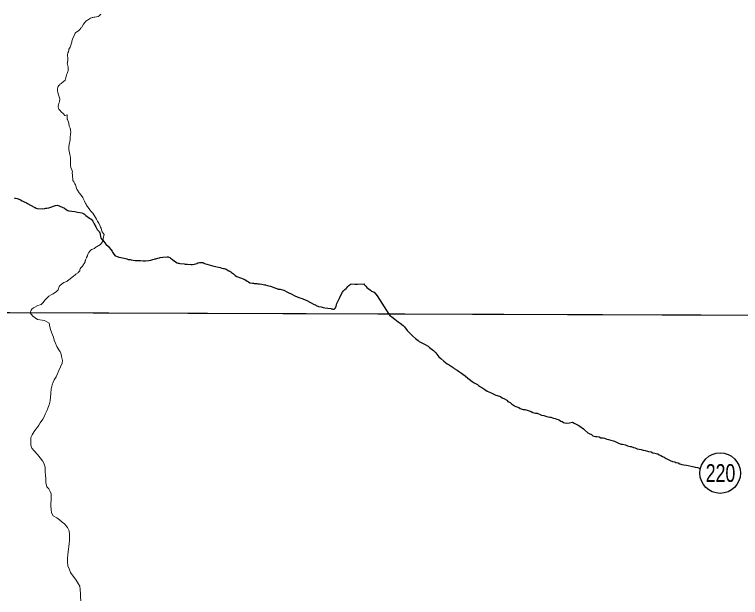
# Model space of a CAD drawing. Extents: x -1643653 to 4543381, y 1624270 to 13878484.
# Drawn here: x 592680 to 595557, y 8908816 to 8911127 of the extents above; entities that cross this region are included whole.
import ezdxf
from ezdxf.enums import TextEntityAlignment as Align

# ---------------------------------------------------------------- set-up
doc = ezdxf.new("R2010")
doc.units = 0
doc.header["$LTSCALE"] = 200
doc.layers.add('1', color=7, linetype='Continuous', lineweight=13)
doc.layers.add('6', color=7, linetype='Continuous', lineweight=13)

msp = doc.modelspace()

# ---------------------------------------------------------------- linework, layer by layer
at = {"layer": '1', "lineweight": 25}
msp.add_spline([(814781, 9009175.5), (814787.2, 9009173.4), (814796.9, 9009173.4), (814799.4, 9009172.4), (814805.1, 9009174.5), (814805.6, 9009176.5), (814811.7, 9009179.5), (814811.7, 9009179.5), (814801.5, 9009181), (814790.7, 9009181.5), (814784.1, 9009183.1), (814777.4, 9009185.1), (814778.4, 9009175.5)], degree=3, dxfattribs=at)
at = {"layer": '6'}
msp.add_line((574653.9, 8910009.3), (626625.7, 8909822.1), dxfattribs=at)
for points in [[(593021, 8911127.6), (593015.2, 8911121.6), (593010.8, 8911119.1), (593005, 8911116.9), (592997.8, 8911116), (592994.4, 8911116), (592989.8, 8911115.5), (592987.6, 8911114.5), (592984.2, 8911113.6), (592980.7, 8911111.7), (592973.4, 8911106.8), (592964.4, 8911101.9), (592962.6, 8911100.6), (592957.6, 8911095.5), (592952.8, 8911088.5), (592945.7, 8911076.3), (592943.7, 8911074.8), (592942.5, 8911072.4), (592938.9, 8911066.9), (592933.7, 8911062.6), (592926.3, 8911058.4), (592923.2, 8911055.9), (592920.4, 8911052.5), (592916.1, 8911043.7), (592916.1, 8911043.7), (592909.6, 8911028.6)], [(593021, 8911127.6), (593015.2, 8911121.6), (593010.8, 8911119.1), (593005, 8911116.9), (592997.8, 8911116), (592994.4, 8911116), (592989.8, 8911115.5), (592987.6, 8911114.5), (592984.2, 8911113.6), (592980.7, 8911111.7), (592973.4, 8911106.8), (592964.4, 8911101.9), (592962.6, 8911100.6), (592957.6, 8911095.5), (592952.8, 8911088.5), (592945.7, 8911076.3), (592943.7, 8911074.8), (592942.5, 8911072.4), (592938.9, 8911066.9), (592933.7, 8911062.6), (592926.3, 8911058.4), (592923.2, 8911055.9), (592920.4, 8911052.5), (592916.1, 8911043.7), (592916.1, 8911043.7), (592909.6, 8911028.6)], [(592909.6, 8911028.6), (592908.5, 8911024.7), (592907.1, 8911020.9), (592906.4, 8911017), (592904.4, 8911009.3), (592899.9, 8910997.6), (592898, 8910993.9), (592895.4, 8910989.9), (592894.3, 8910985.6), (592892.9, 8910978.5), (592891.3, 8910974.3), (592890.1, 8910966.4), (592890.1, 8910963), (592891.2, 8910954.9), (592891, 8910946.7), (592888.9, 8910935.1), (592888.6, 8910931.1), (592889.2, 8910929.2), (592890.3, 8910922.9), (592892, 8910918.3), (592892.1, 8910914.2), (592892.6, 8910909.9), (592892.2, 8910904.3), (592891.6, 8910903.2), (592891.1, 8910901.2), (592887.7, 8910893.3), (592886, 8910888.3), (592883.8, 8910880.5), (592883, 8910875.6), (592881.9, 8910871.2), (592880.5, 8910867.1), (592879.4, 8910865.2), (592874.2, 8910861), (592864, 8910853.8), (592859.3, 8910850.9), (592858.7, 8910849.9), (592858.5, 8910848.3), (592855.2, 8910845), (592852.8, 8910840.8), (592850.9, 8910837.1), (592850.1, 8910832.8), (592850.2, 8910828.5), (592849.9, 8910824.2), (592850.6, 8910819.4), (592852.2, 8910812.2), (592853.7, 8910808.4), (592855.7, 8910804.2), (592858.1, 8910796.9), (592858.8, 8910793.1), (592857.3, 8910780.7), (592855.5, 8910775.7), (592853.5, 8910767.8), (592852.8, 8910763.4), (592852.9, 8910761.5), (592854.1, 8910755.4), (592855.6, 8910750.4), (592855.9, 8910749.9), (592858.7, 8910747.8), (592866.3, 8910739.6), (592871.8, 8910734.4), (592879.5, 8910726.3), (592880.3, 8910726.4), (592887.2, 8910728.8), (592887.9, 8910728.8), (592888, 8910711.7), (592888.2, 8910711.4), (592889.3, 8910711.1), (592894.6, 8910695.8), (592896.6, 8910683.7), (592899.7, 8910676), (592900.8, 8910672.1), (592901, 8910668.3), (592902.1, 8910660.6), (592901.9, 8910653.4), (592899.8, 8910637.4), (592899.7, 8910629.6), (592896.5, 8910611.5), (592895.3, 8910602.9), (592895.4, 8910595), (592895.3, 8910591.2), (592898.7, 8910571.6), (592900, 8910566.8), (592901.4, 8910558.8), (592901.9, 8910545.9), (592901.7, 8910528.6), (592902.9, 8910520.1), (592906.2, 8910511.7), (592908.7, 8910503.3), (592908.6, 8910499), (592909.8, 8910490.3), (592910, 8910481.9), (592910.6, 8910477.6), (592910.5, 8910473.3), (592911.1, 8910469.2), (592911.9, 8910467.9), (592912.4, 8910466.2), (592913.2, 8910465.7), (592913.5, 8910464.9), (592914.1, 8910464.3), (592914.6, 8910463), (592914.6, 8910463)], [(592909.6, 8911028.6), (592908.5, 8911024.7), (592907.1, 8911020.9), (592906.4, 8911017), (592904.4, 8911009.3), (592899.9, 8910997.6), (592898, 8910993.9), (592895.4, 8910989.9), (592894.3, 8910985.6), (592892.9, 8910978.5), (592891.3, 8910974.3), (592890.1, 8910966.4), (592890.1, 8910963), (592891.2, 8910954.9), (592891, 8910946.7), (592888.9, 8910935.1), (592888.6, 8910931.1), (592889.2, 8910929.2), (592890.3, 8910922.9), (592892, 8910918.3), (592892.1, 8910914.2), (592892.6, 8910909.9), (592892.2, 8910904.3), (592891.6, 8910903.2), (592891.1, 8910901.2), (592887.7, 8910893.3), (592886, 8910888.3), (592883.8, 8910880.5), (592883, 8910875.6), (592881.9, 8910871.2), (592880.5, 8910867.1), (592879.4, 8910865.2), (592874.2, 8910861), (592864, 8910853.8), (592859.3, 8910850.9), (592858.7, 8910849.9), (592858.5, 8910848.3), (592855.2, 8910845), (592852.8, 8910840.8), (592850.9, 8910837.1), (592850.1, 8910832.8), (592850.2, 8910828.5), (592849.9, 8910824.2), (592850.6, 8910819.4), (592852.2, 8910812.2), (592853.7, 8910808.4), (592855.7, 8910804.2), (592858.1, 8910796.9), (592858.8, 8910793.1), (592857.3, 8910780.7), (592855.5, 8910775.7), (592853.5, 8910767.8), (592852.8, 8910763.4), (592852.9, 8910761.5), (592854.1, 8910755.4), (592855.6, 8910750.4), (592855.9, 8910749.9), (592858.7, 8910747.8), (592866.3, 8910739.6), (592871.8, 8910734.4), (592879.5, 8910726.3), (592880.3, 8910726.4), (592887.2, 8910728.8), (592887.9, 8910728.8), (592888, 8910711.7), (592888.2, 8910711.4), (592889.3, 8910711.1), (592894.6, 8910695.8), (592896.6, 8910683.7), (592899.7, 8910676), (592900.8, 8910672.1), (592901, 8910668.3), (592902.1, 8910660.6), (592901.9, 8910653.4), (592899.8, 8910637.4), (592899.7, 8910629.6), (592896.5, 8910611.5), (592895.3, 8910602.9), (592895.4, 8910595), (592895.3, 8910591.2), (592898.7, 8910571.6), (592900, 8910566.8), (592901.4, 8910558.8), (592901.9, 8910545.9), (592901.7, 8910528.6), (592902.9, 8910520.1), (592906.2, 8910511.7), (592908.7, 8910503.3), (592908.6, 8910499), (592909.8, 8910490.3), (592910, 8910481.9), (592910.6, 8910477.6), (592910.5, 8910473.3), (592911.1, 8910469.2), (592911.9, 8910467.9), (592912.4, 8910466.2), (592913.2, 8910465.7), (592913.5, 8910464.9), (592914.1, 8910464.3), (592914.6, 8910463), (592914.6, 8910463)], [(592914.6, 8910463), (592915.4, 8910462.3), (592916.1, 8910460.3), (592918.7, 8910456), (592920.7, 8910451.9), (592922.6, 8910447.1), (592924.7, 8910438.7), (592926.3, 8910434.8), (592928.6, 8910430.4), (592936.2, 8910419.6), (592943.9, 8910410.6), (592949.8, 8910401.8), (592952, 8910397.9), (592953.5, 8910394.6), (592956.4, 8910386.7), (592959.2, 8910380.4), (592961.5, 8910377.9), (592961.8, 8910376.4), (592962.9, 8910374.8), (592964.8, 8910371.1), (592978.6, 8910352.2), (592983.7, 8910346.6), (592990.1, 8910338.8), (593000.6, 8910322.5), (593004.8, 8910315), (593008.5, 8910307.3), (593013.4, 8910299.5), (593019.4, 8910288), (593020.8, 8910284), (593022.5, 8910280.1), (593024.6, 8910273.2), (593027.6, 8910264.8), (593035.4, 8910254.4), (593030.7, 8910240.7), (593030.9, 8910230.2), (593020.1, 8910215.3), (592998.5, 8910201.7), (592997.4, 8910200.2), (592996.1, 8910199.2), (592992.6, 8910198.2), (592989.5, 8910197.1), (592988, 8910196.2), (592985.1, 8910195), (592981.8, 8910193.1), (592977.9, 8910188.9), (592974.2, 8910183.6), (592974, 8910182.8), (592973, 8910182.1), (592970.3, 8910177.3), (592968.2, 8910170.4), (592964.9, 8910164), (592964.4, 8910161.9), (592963.2, 8910159.9), (592962.2, 8910157.6), (592961.4, 8910154.6), (592960.4, 8910152.4), (592960.1, 8910150), (592958.9, 8910146.6), (592955.8, 8910140.3), (592954.4, 8910138.1), (592953.5, 8910135.8), (592948.4, 8910129), (592942.4, 8910123.1), (592939.8, 8910119.4), (592938, 8910115.1), (592938.7, 8910111.5), (592933.6, 8910105.6), (592931.8, 8910104.5), (592931.2, 8910103.5), (592922.2, 8910097.5), (592918.4, 8910094), (592914.6, 8910091.5), (592900.2, 8910078.7), (592890, 8910070.6), (592886.7, 8910068.4), (592875.2, 8910064.1), (592864.2, 8910056.5), (592861.2, 8910054.1), (592858.4, 8910051.3), (592856.3, 8910048.5), (592854.8, 8910044.2), (592853.8, 8910039.6), (592852, 8910035.6), (592849, 8910032.1), (592845.4, 8910028.7), (592832.4, 8910019.7), (592824.2, 8910015.7), (592815.9, 8910010.6), (592813, 8910008.1), (592806.8, 8910001.8), (592800.1, 8909994.6), (592792.6, 8909985.4), (592788.8, 8909981.5), (592784.8, 8909978), (592781.2, 8909976.4), (592771.7, 8909973.2), (592759.7, 8909967.1), (592755.4, 8909964.5), (592748.5, 8909959.2), (592745.1, 8909955.2), (592741.7, 8909944.4)], [(592914.6, 8910463), (592915.4, 8910462.3), (592916.1, 8910460.3), (592918.7, 8910456), (592920.7, 8910451.9), (592922.6, 8910447.1), (592924.7, 8910438.7), (592926.3, 8910434.8), (592928.6, 8910430.4), (592936.2, 8910419.6), (592943.9, 8910410.6), (592949.8, 8910401.8), (592952, 8910397.9), (592953.5, 8910394.6), (592956.4, 8910386.7), (592959.2, 8910380.4), (592961.5, 8910377.9), (592961.8, 8910376.4), (592962.9, 8910374.8), (592964.8, 8910371.1), (592978.6, 8910352.2), (592983.7, 8910346.6), (592990.1, 8910338.8), (593000.6, 8910322.5), (593004.8, 8910315), (593008.5, 8910307.3), (593013.4, 8910299.5), (593019.4, 8910288), (593020.8, 8910284), (593022.5, 8910280.1), (593024.6, 8910273.2), (593027.6, 8910264.8), (593035.4, 8910254.4), (593030.7, 8910240.7), (593030.9, 8910230.2), (593020.1, 8910215.3), (592998.5, 8910201.7), (592997.4, 8910200.2), (592996.1, 8910199.2), (592992.6, 8910198.2), (592989.5, 8910197.1), (592988, 8910196.2), (592985.1, 8910195), (592981.8, 8910193.1), (592977.9, 8910188.9), (592974.2, 8910183.6), (592974, 8910182.8), (592973, 8910182.1), (592970.3, 8910177.3), (592968.2, 8910170.4), (592964.9, 8910164), (592964.4, 8910161.9), (592963.2, 8910159.9), (592962.2, 8910157.6), (592961.4, 8910154.6), (592960.4, 8910152.4), (592960.1, 8910150), (592958.9, 8910146.6), (592955.8, 8910140.3), (592954.4, 8910138.1), (592953.5, 8910135.8), (592948.4, 8910129), (592942.4, 8910123.1), (592939.8, 8910119.4), (592938, 8910115.1), (592938.7, 8910111.5), (592933.6, 8910105.6), (592931.8, 8910104.5), (592931.2, 8910103.5), (592922.2, 8910097.5), (592918.4, 8910094), (592914.6, 8910091.5), (592900.2, 8910078.7), (592890, 8910070.6), (592886.7, 8910068.4), (592875.2, 8910064.1), (592864.2, 8910056.5), (592861.2, 8910054.1), (592858.4, 8910051.3), (592856.3, 8910048.5), (592854.8, 8910044.2), (592853.8, 8910039.6), (592852, 8910035.6), (592849, 8910032.1), (592845.4, 8910028.7), (592832.4, 8910019.7), (592824.2, 8910015.7), (592815.9, 8910010.6), (592813, 8910008.1), (592806.8, 8910001.8), (592800.1, 8909994.6), (592792.6, 8909985.4), (592788.8, 8909981.5), (592784.8, 8909978), (592781.2, 8909976.4), (592771.7, 8909973.2), (592759.7, 8909967.1), (592755.4, 8909964.5), (592748.5, 8909959.2), (592745.1, 8909955.2), (592741.7, 8909944.4)], [(592741.7, 8909944.4), (592752.2, 8909931.2), (592771.1, 8909918.4), (592798.7, 8909913.5), (592816.2, 8909903.9), (592820.1, 8909888.4), (592823.5, 8909874.3), (592829.9, 8909857.3), (592834.4, 8909848.3), (592837.3, 8909836.7), (592840.8, 8909826.2), (592847.7, 8909811.2), (592855.7, 8909798.1), (592859.9, 8909789.4)], [(592741.7, 8909944.4), (592752.2, 8909931.2), (592771.1, 8909918.4), (592798.7, 8909913.5), (592816.2, 8909903.9), (592820.1, 8909888.4), (592823.5, 8909874.3), (592829.9, 8909857.3), (592834.4, 8909848.3), (592837.3, 8909836.7), (592840.8, 8909826.2), (592847.7, 8909811.2), (592855.7, 8909798.1), (592859.9, 8909789.4)], [(592859.9, 8909789.4), (592864.1, 8909780.1), (592866.1, 8909770.8), (592869.2, 8909755.3), (592868.2, 8909745), (592862, 8909730.5), (592854.8, 8909716.1), (592849.2, 8909700.1), (592844.1, 8909691.1), (592836.6, 8909679.1), (592832.5, 8909670.2), (592828.5, 8909658.7), (592824.9, 8909643.7), (592823.3, 8909625.2), (592821.7, 8909610.2), (592821.2, 8909595.4)], [(592859.9, 8909789.4), (592864.1, 8909780.1), (592866.1, 8909770.8), (592869.2, 8909755.3), (592868.2, 8909745), (592862, 8909730.5), (592854.8, 8909716.1), (592849.2, 8909700.1), (592844.1, 8909691.1), (592836.6, 8909679.1), (592832.5, 8909670.2), (592828.5, 8909658.7), (592824.9, 8909643.7), (592823.3, 8909625.2), (592821.7, 8909610.2), (592821.2, 8909595.4)], [(592821.2, 8909595.4), (592817.1, 8909579.7), (592811, 8909567.2), (592807, 8909555.7), (592800.9, 8909542.2), (592796.8, 8909532.8), (592791.8, 8909523.3), (592781.2, 8909508.3), (592776.2, 8909499.8), (592770.1, 8909491.9), (592764.1, 8909482.9), (592757.1, 8909474.4), (592749.5, 8909460.9), (592744.4, 8909450.5), (592743.8, 8909435), (592743.8, 8909419.4), (592748.2, 8909407.4), (592757.2, 8909397.9), (592770.1, 8909383.3), (592780.6, 8909369.7), (592790.5, 8909357.2), (592795.7, 8909348.7)], [(592821.2, 8909595.4), (592817.1, 8909579.7), (592811, 8909567.2), (592807, 8909555.7), (592800.9, 8909542.2), (592796.8, 8909532.8), (592791.8, 8909523.3), (592781.2, 8909508.3), (592776.2, 8909499.8), (592770.1, 8909491.9), (592764.1, 8909482.9), (592757.1, 8909474.4), (592749.5, 8909460.9), (592744.4, 8909450.5), (592743.8, 8909435), (592743.8, 8909419.4), (592748.2, 8909407.4), (592757.2, 8909397.9), (592770.1, 8909383.3), (592780.6, 8909369.7), (592790.5, 8909357.2), (592795.7, 8909348.7)], [(592795.7, 8909348.7), (592800.4, 8909332.1), (592800.8, 8909314.1), (592801.7, 8909301.1), (592803.2, 8909287.1), (592803.1, 8909272.5), (592807.5, 8909255), (592815, 8909247), (592820.4, 8909235.9), (592824.4, 8909226.9), (592824.8, 8909216.4), (592824.3, 8909203.4), (592823.7, 8909188.9), (592823.7, 8909178.9), (592824.6, 8909165.3), (592826, 8909151.8), (592833, 8909139.8), (592846.9, 8909132.5)], [(592795.7, 8909348.7), (592800.4, 8909332.1), (592800.8, 8909314.1), (592801.7, 8909301.1), (592803.2, 8909287.1), (592803.1, 8909272.5), (592807.5, 8909255), (592815, 8909247), (592820.4, 8909235.9), (592824.4, 8909226.9), (592824.8, 8909216.4), (592824.3, 8909203.4), (592823.7, 8909188.9), (592823.7, 8909178.9), (592824.6, 8909165.3), (592826, 8909151.8), (592833, 8909139.8), (592846.9, 8909132.5)], [(592846.9, 8909132.5), (592858, 8909124.6), (592868, 8909114.6), (592878, 8909107.7), (592884.1, 8909100.8), (592889.3, 8909093), (592896.2, 8909079.9), (592897.2, 8909066.4), (592898.1, 8909053.4), (592898.1, 8909040.9), (592896.5, 8909029.9), (592894.4, 8909017.9), (592892.9, 8909007.9), (592891.8, 8908997.9), (592890.3, 8908983.9), (592889.7, 8908972.9), (592889.7, 8908957.4), (592891.1, 8908941.8), (592895.5, 8908929.8), (592902, 8908915.3), (592911.4, 8908900.2), (592921.8, 8908888.7), (592923.7, 8908885.4)], [(592846.9, 8909132.5), (592858, 8909124.6), (592868, 8909114.6), (592878, 8909107.7), (592884.1, 8909100.8), (592889.3, 8909093), (592896.2, 8909079.9), (592897.2, 8909066.4), (592898.1, 8909053.4), (592898.1, 8909040.9), (592896.5, 8909029.9), (592894.4, 8909017.9), (592892.9, 8909007.9), (592891.8, 8908997.9), (592890.3, 8908983.9), (592889.7, 8908972.9), (592889.7, 8908957.4), (592891.1, 8908941.8), (592895.5, 8908929.8), (592902, 8908915.3), (592911.4, 8908900.2), (592921.8, 8908888.7), (592923.7, 8908885.4)], [(592923.7, 8908885.4), (592931.3, 8908872.1), (592938.7, 8908860.6), (592940.2, 8908848), (592941.1, 8908831), (592941.5, 8908817), (592943, 8908803)], [(592923.7, 8908885.4), (592931.3, 8908872.1), (592938.7, 8908860.6), (592940.2, 8908848), (592941.1, 8908831), (592941.5, 8908817), (592943, 8908803)]]:
    msp.add_lwpolyline(points, dxfattribs=at)
at = {"layer": '6', "lineweight": 25}
for points in [[(592678.5, 8910400.8), (592682.3, 8910399.2), (592689.8, 8910397.3), (592693.7, 8910396.1), (592702.8, 8910392.2), (592709.9, 8910388.9), (592717.4, 8910384.8), (592726.8, 8910380.3), (592730.8, 8910377.9), (592757.3, 8910363.8), (592759.1, 8910362.1), (592761.8, 8910361.3), (592765.3, 8910359.5), (592769, 8910358.3), (592769.7, 8910357.8), (592788.5, 8910356.9), (592800.2, 8910357.8), (592803.8, 8910358.6), (592808, 8910359.1), (592815.2, 8910360.7), (592841.9, 8910369.3), (592849.9, 8910370.7), (592858.6, 8910366.9)], [(592858.6, 8910366.9), (592877, 8910359), (592884.1, 8910354.3), (592891.5, 8910350.2), (592895, 8910348.6), (592918.9, 8910345.6), (592929.1, 8910343.3), (592946, 8910340.7), (592953, 8910337.9), (592956.3, 8910335.7), (592956.3, 8910335.7), (592959.2, 8910333.1), (592962.7, 8910329.6), (592977, 8910319), (592980.8, 8910317.3), (592983.2, 8910315.1), (592989.3, 8910307.8), (592991.2, 8910304.8), (592993.5, 8910300.4), (592995.7, 8910297.1), (592997.5, 8910292.8), (592999.5, 8910289.4), (593001.4, 8910284.6), (593007.3, 8910274.7), (593013.5, 8910268.2), (593015.5, 8910265.5), (593017.7, 8910261.8), (593018.8, 8910258.2), (593019.4, 8910255), (593020.1, 8910247.1), (593021.9, 8910241.5), (593023.2, 8910239.3), (593027, 8910234.3), (593029.2, 8910232.3)], [(593029.2, 8910232.3), (593042, 8910216.7), (593051.5, 8910207.2), (593059.7, 8910197.1), (593061.8, 8910195), (593066, 8910188.8), (593067.7, 8910184.8), (593073.1, 8910176.6), (593078.3, 8910170.9), (593079.5, 8910170.8), (593080.4, 8910170), (593086.8, 8910167.1), (593089.9, 8910166.1), (593093.6, 8910165.5), (593100.3, 8910163.7), (593114.2, 8910160.8), (593124.2, 8910158.3), (593130.2, 8910156.4), (593137.6, 8910155.2), (593141.5, 8910154), (593158.4, 8910151.5), (593161.8, 8910151.9), (593165.2, 8910151.7), (593168.8, 8910151.9), (593175.3, 8910151.5), (593178.8, 8910151.7), (593188.9, 8910150.8), (593199.2, 8910150.7), (593212.4, 8910151.7), (593219.5, 8910153.5), (593223.2, 8910154.3), (593236.8, 8910158.1), (593240.2, 8910158.7), (593243.5, 8910159.9), (593247.3, 8910160.7), (593253.9, 8910163), (593257.3, 8910163.8), (593267.5, 8910165.5), (593284.9, 8910166.4), (593288.4, 8910166), (593291.5, 8910165)], [(593291.5, 8910165), (593294.8, 8910163.5), (593298.4, 8910160.7), (593298.4, 8910160.7), (593305.9, 8910155.4), (593313.1, 8910149.6), (593324.6, 8910142.8), (593328, 8910141.3), (593331.4, 8910140.8), (593335, 8910140), (593351.7, 8910138.3), (593355.8, 8910137.4), (593365.5, 8910137), (593378.8, 8910135.9), (593385.6, 8910136.1), (593393.1, 8910137.5), (593402.7, 8910140.5), (593406.4, 8910142.1), (593412.9, 8910143.3), (593420.1, 8910144), (593426.7, 8910143.4), (593427.9, 8910142.5), (593433.2, 8910140.1), (593470, 8910128.8), (593494.4, 8910123.5), (593501, 8910121.7), (593508.3, 8910120.7), (593511.2, 8910119.9), (593514.7, 8910118.5), (593518.2, 8910117.3), (593522.5, 8910115.2), (593529.6, 8910111), (593532.6, 8910108.9), (593536.4, 8910106.9), (593540, 8910104.1), (593547.8, 8910098.9), (593554.7, 8910093)], [(593554.7, 8910093), (593561.1, 8910088.9), (593575.2, 8910083.7), (593593.1, 8910076.1), (593601.3, 8910070.4), (593606.6, 8910067.2), (593612.7, 8910063.9), (593622.6, 8910062.1), (593626.3, 8910061.8), (593629.6, 8910061.2), (593640, 8910060.7), (593643.5, 8910059.9), (593650.2, 8910059.4), (593660.1, 8910058.2), (593670.6, 8910056), (593673.9, 8910055.6), (593680.7, 8910053.3), (593687.8, 8910051.7), (593694.5, 8910049.6), (593711.2, 8910043.1), (593719.9, 8910040.3), (593721.8, 8910039.2), (593724.7, 8910038.3), (593732, 8910037.7), (593742.2, 8910035.3), (593746.6, 8910033.6), (593761, 8910026.2), (593767.3, 8910023.6), (593775.5, 8910019.8), (593791.3, 8910011.7), (593800.5, 8910007.3), (593810.8, 8910004.2), (593819.1, 8910001), (593825.5, 8909998), (593835.5, 8909994), (593853, 8909985.5), (593867.8, 8909977.5), (593872, 8909976.1), (593875.5, 8909974.1), (593885.1, 8909970.1), (593895.5, 8909967.6), (593902.5, 8909965.3), (593909.1, 8909963.8), (593932.8, 8909961), (593936.4, 8909960), (593939.1, 8909959.7), (593941.1, 8909958.7), (593943.7, 8909958.9), (593946.2, 8909959.5), (593948.1, 8909960.9), (593951.3, 8909964.8), (593954, 8909971.3), (593957.5, 8909981.8), (593969.1, 8910005.1), (593970.9, 8910009.4), (593979.7, 8910026.9), (593982.4, 8910030.4), (593988.7, 8910036.9), (593993.8, 8910041.2), (593996.3, 8910044), (594000.9, 8910048.2), (594004.6, 8910052.2), (594005.8, 8910052.6), (594007.4, 8910054.3), (594010.6, 8910056.6)], [(594010.6, 8910056.6), (594013.9, 8910058.9), (594030.2, 8910058), (594039.3, 8910057.8), (594065.1, 8910059.8)], [(594065.1, 8910059.8), (594065.3, 8910056.9), (594071.5, 8910049.8), (594076.6, 8910045.4), (594082, 8910041.4), (594090.9, 8910033.6), (594094.4, 8910030.9), (594104.6, 8910026.1), (594117, 8910011.3), (594163.5, 8909939)], [(594163.5, 8909939), (594167.3, 8909934.5), (594175.7, 8909928), (594187.2, 8909918.9), (594200.6, 8909908.3), (594207.6, 8909903.2), (594220, 8909894.1), (594224.9, 8909888.6), (594235.3, 8909875), (594240.8, 8909869.4), (594251.7, 8909858.4), (594257.7, 8909853.3), (594268.6, 8909842.7), (594279.1, 8909834.7), (594284, 8909831.1), (594296.5, 8909824), (594304.5, 8909820), (594319.4, 8909811.8), (594324.9, 8909807.3), (594335.3, 8909799.2), (594340.3, 8909795.2), (594350.2, 8909785.6)], [(594350.2, 8909785.6), (594361.6, 8909770.5), (594369.1, 8909762.9), (594381, 8909752.9), (594393.9, 8909742.8), (594402.4, 8909737.7), (594417.8, 8909728.1), (594422.8, 8909724), (594433.7, 8909717), (594439.7, 8909712.9), (594451.2, 8909704.8), (594456.1, 8909700.8), (594465.6, 8909694.2), (594476, 8909686.1), (594482, 8909681.1), (594493.9, 8909672.5), (594500.9, 8909667.4), (594514.3, 8909659.8), (594518.8, 8909656.8), (594526.8, 8909651.2), (594532.2, 8909648.2), (594543.7, 8909641.1), (594553.7, 8909634.6), (594559.6, 8909631.5), (594571.6, 8909625.9), (594576.6, 8909622.9), (594587.5, 8909617.8), (594593, 8909616.8), (594605.5, 8909612.2), (594612.5, 8909607.1), (594622, 8909603.6), (594630.4, 8909598.5), (594635.4, 8909593.4), (594643.8, 8909589.4), (594649.3, 8909584.3), (594661.8, 8909576.2), (594667.2, 8909573.2), (594678.7, 8909569.6), (594684.2, 8909565.6), (594695.7, 8909561.5), (594702.7, 8909561), (594715.6, 8909557.9), (594727.6, 8909553.8), (594733.6, 8909549.7), (594745.1, 8909546.2), (594751.1, 8909546.1), (594763, 8909541.5), (594768.5, 8909538.5), (594777.5, 8909537.9), (594782, 8909536.4), (594790, 8909533.3), (594795.5, 8909532.8), (594801.5, 8909531.3), (594806, 8909530.7), (594811.5, 8909527.7), (594816.5, 8909527.2), (594822.4, 8909525.1), (594828.9, 8909523.1), (594833.9, 8909521), (594840.4, 8909518.5), (594844.9, 8909515.5), (594850.4, 8909513.4), (594855.8, 8909509.4), (594861.3, 8909508.8), (594865.8, 8909506.8), (594879.8, 8909508.2)], [(594879.8, 8909508.2), (594890.9, 8909511.2), (594897.3, 8909507.1), (594913.8, 8909499.5), (594920.8, 8909494.9), (594934.7, 8909484.8), (594940.7, 8909479.3), (594952.1, 8909468.7), (594957.1, 8909465.7), (594966.5, 8909462.1), (594972.5, 8909457.5), (594982.5, 8909454), (594987.5, 8909453.9), (594997, 8909452.4), (595003, 8909449.3), (595013.4, 8909448.8), (595017.9, 8909447.2), (595027.9, 8909443.2), (595033.4, 8909442.6), (595043.4, 8909439.5), (595052.4, 8909436.5), (595057.4, 8909435.4), (595068.3, 8909430.9), (595073.8, 8909427.8), (595084.3, 8909424.2), (595089.3, 8909424.2), (595101.8, 8909420.6), (595108.8, 8909417.1), (595119.7, 8909414), (595124.2, 8909414), (595133.2, 8909410.9), (595140.2, 8909409.4), (595148.2, 8909405.3), (595155.2, 8909404.2), (595163.2, 8909402.7), (595171.2, 8909400.1), (595179.1, 8909398.6), (595188.1, 8909395.5), (595193.1, 8909395), (595203.6, 8909393.4), (595210.1, 8909389.9), (595218.1, 8909388.8), (595223.6, 8909387.3), (595230.1, 8909386.2), (595235.5, 8909382.2), (595241.5, 8909379.2), (595248, 8909375.6), (595255, 8909372.1), (595262.9, 8909367), (595270.9, 8909362.9), (595278.9, 8909358.9), (595287.8, 8909355.3), (595296.3, 8909354.2), (595300.8, 8909350.7), (595310.3, 8909350.2), (595317.3, 8909346.6), (595324.8, 8909343.1), (595332.8, 8909342), (595343.3, 8909340.4), (595349.8, 8909338.9), (595362.2, 8909337.3), (595366.7, 8909335.8), (595373.2, 8909334.7), (595378.2, 8909333.2), (595386.7, 8909331.6), (595397.5, 8909327.7)]]:
    msp.add_lwpolyline(points, dxfattribs=at)
at = {"layer": '6'}
msp.add_lwpolyline([(596575.8, 8909932.4), (585614.8, 8909969.8), (585583.8, 8898914.4), (596544.8, 8898874.9)], close=True, dxfattribs=at)
at = {"layer": '6', "lineweight": 25}
msp.add_circle((595476.7, 8909309.2), 80.3, dxfattribs=at)

# ---------------------------------------------------------------- texts
at = {"layer": '6', "width": 0.75}
msp.add_text('220', height=70, dxfattribs=at).set_placement((595478, 8909274.6), align=Align.CENTER)

doc.saveas('drawing.dxf')
